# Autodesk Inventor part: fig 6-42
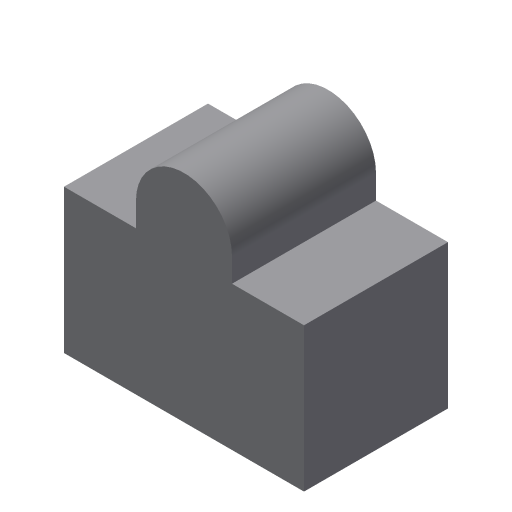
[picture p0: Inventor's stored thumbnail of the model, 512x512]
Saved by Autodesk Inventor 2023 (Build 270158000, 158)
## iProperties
Created: 2005-12
Part Number: fig 6-42
Document SubType Name: Modeling
Designer: CADCIM
Density: 1 g/cm^3
Material: Generic
Appearance: Default
Author: CADCIM
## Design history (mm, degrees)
sketch "Sketch1"
  geometry: L1 (10, 15)-(25, 15); L2 (25, 15)-(25, -15); L3 (25, -15)-(-25, -15); L4 (-25, -15)-(-25, 15); L5 (-25, 15)-(-10, 15); L6 (10, 15)-(10, 30); L7 (10, 30)-(-10, 30); L8 (-10, 30)-(-10, 15)
  constraints: 16 end point, 3 parallel, 3 perpendicular, 2 equal length, 1 collinear, 1 horizontal
  dimensions: "d0" = 50 distance of L2.end L3.end; "d2" = 30 distance of L1.end L2.end; "d3" = 15 distance of L1.start L1.end; "d11" = 15 distance of L7.end L5.end
extrude "Extrusion1" new body sketch "Sketch1" stored distance "d7" = 30; taper "d8" = 0 deg
fillet "Fillet5"
body "Solid1"
